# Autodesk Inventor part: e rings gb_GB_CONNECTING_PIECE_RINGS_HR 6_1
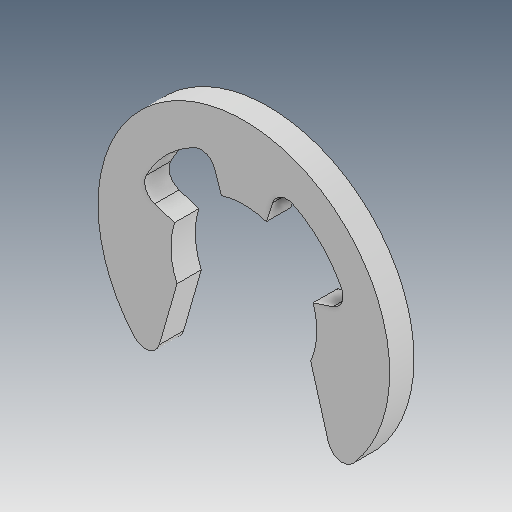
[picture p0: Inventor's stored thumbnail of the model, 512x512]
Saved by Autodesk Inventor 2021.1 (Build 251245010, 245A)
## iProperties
Created: 2019-04
Part Number: e rings gb_GB_CONNECTING_PIECE_RINGS_HR 6_1
Material: Ogólny
Document SubType Name: Modeling
Designer: user
Density: 1 g/cm^3
Appearance: Domyślna
Author: user
Revision Number: ÈÎºÎ
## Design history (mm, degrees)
feature "ÊäÈë1"
node "Bryła1"
